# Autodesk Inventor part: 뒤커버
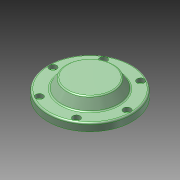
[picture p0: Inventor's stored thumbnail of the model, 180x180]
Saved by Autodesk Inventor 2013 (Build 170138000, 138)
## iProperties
Created: 2013-01
Part Number: 뒤커버
Document SubType Name: Modeling
Designer: 한국산업디자인학원[gmhk.co.kr]
Density: 2.71 g/cm^3
Material: 알루미늄 6061
Mass: 415.969 g
Surface Area: 272.105 cm^2
Volume: 153.494 cm^3
Author: 한국산업디자인학원[gmhk.co.kr]
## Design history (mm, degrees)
sketch "스케치2"
  geometry: L1 (-55, 0)-(55, 0) reference; L2 (35.98, -6)-(-35.98, -6) reference; L3 (-42.5, -25)-(-42.5, 0) reference; L4 (-37, -6)-(-37, 0); L5 (-55, 0)-(-55, 10); L6 (-55, 10)-(-37.5, 10); L7 (-37, -6)-(-42.5, -6); L8 (-37.5, 10)-(-29.994, 23); L9 (-29.994, 23)-(0, 23); L10 (-55, 0)-(-42.5, 0); L11 (-42.5, -6)-(-42.5, 0); L12 (0, 0)-(0, 23); L13 (0, 0)-(-37, 0)
  constraints: 22 end point, 4 perpendicular, 3 collinear, 2 parallel, 2 point on line, 1 vertical, 2 other
  dimensions: "d2" = 10 distance of L1.start L5.end; "d4" = 120 deg angle of L8 L6; "d5" = 13 distance between parallel lines of L6 L9; "d6" = 74 diameter of L4 L12; "d7" = 75 diameter of L6.end L12
revolve "회전1" sketch "스케치2" stored, may be unused: angle "d8" = 90 deg
fillet "모깎기1" dims "d9" = 2
sketch "스케치3"
  geometry: C1 r 2.067 at (48.5, 0) reference; 1 further point
hole "구멍1" sketch "스케치3" at (48.5, 0) diameter "d10" = 5.5; stored, may be unused: countersink angle "d14" = 90 deg, drill point angle "d16" = 118 deg; dims "d11" = 6, "d12" = 9.5, "d13" = 5.4, "d15" = 8
fillet "모깎기2" dims "d20" = 3
chamfer "모따기1" distance "d21" = 1; stored, may be unused: second distance "d22" = 2, angle "d23" = 45 deg
node "솔리드1"
pattern_circular "원형 패턴1" dims angle "d18" = 360 deg
node "참조1"
node "참조2"
node "참조3"
